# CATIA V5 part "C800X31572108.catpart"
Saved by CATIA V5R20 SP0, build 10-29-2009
Part number: C800X31572108
Source: Unknown
Property "A": "90"
Property "ARTICLENO": "C800X31572108"
Property "B": "45"
Property "BOMINFO": "C800X31572108"
Property "C": "124"
Property "CA": "C800X31572108"
Property "D1": "170"
Property "DES": "ROTATING EYEBOLT WITH RING Ton 31,5 M72x108"
Property "E": "165"
Property "H": "333"
Property "L": "108"
Property "LINA": "C800X31572108"
Property "NB": "C800X31572108"
Property "NBSYN": "$CODE."
Property "NN": "C800X"
Property "NT": "Rotating eyebolt with ring"
Property "SIZE": "M72"
Property "SUPPLIER": "CF"
Property "SW": "134"
Property "WEIGHT": "29000"
Property "WLL": "31.50"
Bounding box of the stored display mesh (mm): x -90 to 90, y -108 to 378, z -85 to 85
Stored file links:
  C:\Users\Utente\Desktop\3D files 800X\C800X31572108.catpart

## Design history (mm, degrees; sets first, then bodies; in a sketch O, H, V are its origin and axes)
Body1 "Geometry.1" (main body)
  Solid1 "C800X31572108.catpart": solid without history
